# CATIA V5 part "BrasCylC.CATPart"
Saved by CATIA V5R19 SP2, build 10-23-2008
Part number: CylC
Bounding box of the stored display mesh (mm): x -45 to 45, y -44.99 to 44.99, z -15 to 355.981
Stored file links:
  C:\Users\Vianney\Documents\Garantie\Cours\2A\IAO\IAO-proj-Catia\BrasCylC.CATPart
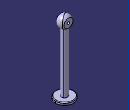
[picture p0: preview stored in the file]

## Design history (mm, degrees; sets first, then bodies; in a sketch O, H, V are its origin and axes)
Parameters
  LbrasC = 300 mm
  Dmc = 12 mm
  DbrasCylC = 30 mm
Body1 (main body)
  Sketch1 on zx-plane, origin (0, 0, 0), H (-1, 0, 0), V (0, 0, 1)
    point P1 (0, 325.9808)
    line L1 (15, 0) -> (15, 300)
    arc A1 centre (0, 325.9808) radius 30 from (15, 300) to (0, 355.9808) ccw
    point P4 (15, 351.9615)
    point P5 (0, 355.9808)
    line L2 (0, 355.9808) -> (0, 0)
    line L3 (0, 0) -> (15, 0)
    distance L1 L2 = 15 {= DbrasCylC /2}
    length L1 = 300 {= LbrasC}
    radius A1 = 30
    coincidence: P1 V, A1 P4, P4 L1, P5 V
    vertical: L1 V, L2 V
    horizontal: L3 H
  Shaft1: profile Sketch1, axis Sketch1.L2, angle 360
  Sketch2 on zx-plane, origin (0, 0, 0), H (-1, 0, 0), V (0, 0, 1)
    circle A1 centre (0, 325.9808) radius 6
    point P1 (0, 325.9808)
    reference projected arc E1 centre (0, 325.9808) radius 30 from (22.5, 306.1376) to (0, 355.9808) ccw from Sketch1.A1
    radius A1 = 6 {= Dmc /2}
    coincidence: P1 V
    concentricity: A1 E1
  Pocket1: profile Sketch2, direction (0, -1, 0), through (limit type 6), opposite side length 44
  Sketch3 on yz-plane, origin (0, 0, 0), H (0, 1, 0), V (0, 0, 1)
    point P1 (-32, 303)
    line L1 (-32, 303) -> (-20, 303)
    line L2 (-20, 303) -> (-20, 351)
    line L3 (-20, 351) -> (-32, 351)
    line L4 (-32, 351) -> (-32, 303)
    point P2 (-20, 303)
    point P3 (-20, 351)
    point P4 (-32, 351)
    reference projected line E1 (-15, 300) -> (15, 300) from edge [face of Shaft1 from Sketch1.L1 | face of Shaft1 from Sketch1.A1]
    reference projected line E2 (0, 325) -> (0, 380.9808) from Sketch1.A1
    reference projected line E3 (0, 355.9808) -> (0, 0) from Sketch1.L2
    point P7 (32, 303)
    point P8 (20, 303)
    point P9 (20, 351)
    point P10 (32, 351)
    line L5 (32, 303) -> (20, 303)
    line L6 (20, 303) -> (20, 351)
    line L7 (20, 351) -> (32, 351)
    line L8 (32, 351) -> (32, 303)
    distance E1 L1 = 3
    distance L2 E2 = 20
    distance L4 L2 = 12
    distance L3 L1 = 48
    horizontal: L1 H, L3 H
    vertical: L2 V, L4 V
    symmetry: P1 P7 E3, P2 P8 E3, P3 P9 E3, P4 P10 E3, L1 L5 E3, L2 L6 E3, L3 L7 E3, L4 L8 E3
  Pocket2: profile Sketch3, direction (1, 0, 0), length 30, opposite side length 44
  Sketch4 on face of Shaft1 from Sketch1.L3, origin (0, 0, 0), H (1, 0, 0), V (0, -1, 0)
    circle A1 centre (0, 0) radius 45
    radius A1 = 45
  Pad1: profile Sketch4, direction (0, 0, -1), length 15
  Fillet1: radius 3, on end face of Pad1; edge [start face of Pad1 | face of Pad1 from Sketch4.A1]
  Fillet2: radius 15, on edge [face of Shaft1 from Sketch1.L1 | face of Shaft1 from Sketch1.A1]
Current feature: Fillet1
